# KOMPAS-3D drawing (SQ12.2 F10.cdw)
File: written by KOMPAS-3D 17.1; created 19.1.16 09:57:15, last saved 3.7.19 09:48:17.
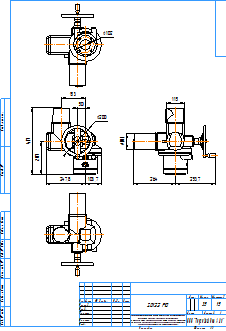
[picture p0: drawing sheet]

Sheet 1: A3, portrait

Title block, sheet 1: name: SQ12.2 F10; material: Сталь 10  ГОСТ 1050-88; mass: 35; sheets: 1; sheet format: A3; stored path: C:\Users\kka\KOMPAS_Work\!Trash\Электроприводы\SQ12.2 F10.cdw

Views: Проекционный вид 2, Проекционный вид 3, Проекционный вид 4
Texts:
  Klimkovich
  ADL
  Рама для чертежей
  Лит-Масса-Масштаб
  Материал-Предприятие
  Масштаб
  Изм.
  Лист
  № докум.
  Подп.
  Дата
  Лит.
  Разраб.
  Пров.
  Т.контр.
  Листов
  Внимание! Данный продукт является объектом авторского права ООО «Торговый Дом АДЛ».
  Запрещается изменение, копирование, распространение
  (в том числе путем копирования на другие сайты и ресурсы в Интернете)
  или любое иное использование информации и объектов без предварительного
  согласия правообладателя (ООО «Торговый Дом АДЛ»).
  Н.контр.
  Утв.
  ООО "Торговый дом АДЛ"
  Изменение
  Номер документа
  Подпись
  Обозначение документа
  Наименование изделия
  Масса изделия по ГОСТ 2.109-73
  Порядковый номер листа
  Общее количество листов в документе
  Характер работы, выполненной лицом, подписавшим документ
  Наименование или индекс предприятия, выпускающего документ
  Инв. № подл.
  Подп. и дата
  Взам. инв. №
  Инв. № дубл.
  Инвентарный номер подлинника по ГОСТ 2.501-68
  Подпись принявшего подлинник в отдел технической документации
  Инвентарный номер подлинника, взамен которого выпущен данный подлинник
  Инвентарный номер дубликата по ГОСТ 2.502-68
  Подпись принявшего дубликат в отдел технической документации
  Справ. №
  Перв. примен.
  Обозначение документа, взамен или на основании которого выпущен данный документ
  Обозначение документа, в котором впервые записан данный документ
  Подпись лица, копировавшего чертеж
  Обозначение формата листа
  !Рама для чертежа
Dimensions and other numbers on the sheet: 153; 200; 103,7; 247,8; 50; 207; 417; 1 1; 115; 101; 253,7; 264; 102; 1:5; 1; 35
